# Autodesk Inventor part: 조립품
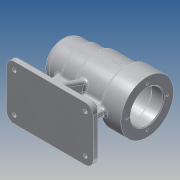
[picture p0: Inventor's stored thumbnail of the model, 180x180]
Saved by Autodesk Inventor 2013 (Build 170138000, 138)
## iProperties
Created: 2016-06
Part Number: 조립품
Material: 알루미늄 6061
Document SubType Name: Modeling
Designer: Administrator
Density: 2.71 g/cm^3
Mass: 669.883 g
Surface Area: 649.572 cm^2
Volume: 247.189 cm^3
Author: Administrator
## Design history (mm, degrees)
sketch "스케치1"
  geometry: L1 (56, 34)-(56, 0); L2 (56, 0)-(-56, 0); L3 (-56, 0)-(-56, 25); L4 (56, 34)-(28, 34); L5 (28, 34)-(28, 30); L6 (28, 30)-(-11, 30); L7 (-11, 30)-(-11, 27); L8 (-11, 27)-(-31, 27); L9 (-31, 27)-(-31, 25); L10 (-31, 25)-(-56, 25); 2 further points
  constraints: 20 end point, 5 parallel, 3 perpendicular, 1 coincident, 1 midpoint
  dimensions: "d0" = 112 distance between parallel lines of L1 L3; "d2" = 68 diameter of L4 L2; "d3" = 60 diameter of L6 L2; "d4" = 54 diameter of L8 L2; "d5" = 50 diameter of L10 L2; "d6" = 25 distance between parallel lines of L3 L9; "d7" = 45 distance between parallel lines of L7 L3; "d8" = 84 distance between parallel lines of L3 L5
sketch "스케치2"
  geometry: 1 further point
sketch "스케치3"
  geometry: 1 further point
revolve "회전1" stored, may be unused: angle "d9" = 90 deg
sketch "스케치4"
  geometry: L1 (-31, -25)-(-56, -25) reference; L2 (-56, -25)-(-56, 25) reference; L3 (-56, 25)-(-31, 25) reference; L4 (-31, 25)-(-31, 27) reference; L5 (-31, 27)-(-11, 27) reference; L6 (-11, 27)-(-11, 30) reference; L7 (-11, 30)-(28, 30) reference; L8 (28, 30)-(28, 34) reference; L9 (28, 34)-(56, 34) reference; L10 (56, 34)-(56, -34) reference; L11 (56, -34)-(28, -34) reference; L12 (28, -34)-(28, -30) reference; L13 (28, -30)-(-11, -30) reference; L14 (-11, -30)-(-11, -27) reference; L15 (-11, -27)-(-31, -27) reference; L16 (-31, -27)-(-31, -25) reference; L17 (-36, 0)-(-36, -60); L18 (-36, 0)-(36, 0); L19 (28, -34)-(28, 34) reference; L20 (36, 0)-(36, -60); L21 (-56, -60)-(56, -60); L22 (56, -60)-(56, -70); L23 (56, -70)-(-56, -70); L24 (-56, -70)-(-56, -60); 2 further points
  constraints: 14 end point, 4 parallel, 2 perpendicular, 2 point on line, 1 coincident, 1 horizontal, 1 midpoint, 1 vertical alignment
  dimensions: "d10" = 70 distance from line of point (0, 0) L23; "d11" = 10 distance between parallel lines of L23 L21; "d12" = 112 distance between parallel lines of L22 L24; "d13" = 20 distance of L17.end L21.start; "d14" = 20 distance of L21.end L20.end (derived)
  node "절단 모서리 투영1"
extrude "돌출1" join sketch "스케치4" stored distance "d15" = 8; taper "d16" = 0 deg
extrude "돌출2" join sketch "스케치4" stored distance "d17" = 70; taper "d18" = 0 deg
sketch "스케치5"
  geometry: L1 (-60, -4)-(-60, -35) reference; L2 (-60, -35)-(-70, -35) reference; L3 (-70, -35)-(-70, 35) reference; L4 (-70, 35)-(-60, 35) reference; L5 (-60, 35)-(-60, 4) reference; L6 (-60, 4)-(-29.732, 4) reference; L7 (-29.732, -4)-(-60, -4) reference; L8 (0, 6.162)-(-60, 28); L9 (-60, -35)-(-60, 35) reference; L10 (0, -6.162)-(-60, -28); L11 (0, 6.162)-(0, -6.162); A1 r 30 centre (0, 0) between (-29.732, -4) and (-29.732, 4) reference; 2 further points
  constraints: 6 end point, 2 point on line, 1 coincident, 1 midpoint, 1 parallel
  dimensions: "d19" = 110 deg angle of L8 L5; "d20" = 110 deg angle of L10 L1; "d21" = 7 distance of L8.end L4.end; "d22" = 7 distance of L1.end L10.end (derived)
extrude "돌출3" join sketch "스케치5" stored distance "d23" = 8; taper "d24" = 0 deg
sketch "스케치6"
  geometry: L1 (-56, 25)-(-31, 25) reference; L2 (-31, 25)-(-31, 27) reference; L3 (-31, 27)-(-11, 27) reference; L4 (-11, 27)-(-11, 30) reference; L5 (-11, 30)-(28, 30) reference; L6 (28, 30)-(28, 34) reference; L7 (28, 34)-(56, 34) reference; L8 (56, 34)-(56, -34) reference; L9 (56, -34)-(36, -34) reference; L10 (36, -34)-(36, -60) reference; L11 (36, -60)-(56, -60) reference; L12 (56, -60)-(56, -70) reference; L13 (56, -70)-(-56, -70) reference; L14 (-56, -70)-(-56, -60) reference; L15 (-56, -60)-(-36, -60) reference; L16 (-36, -60)-(-36, -25) reference; L17 (-36, -25)-(-56, -25) reference; L18 (-56, -25)-(-56, 25) reference; L19 (56, -34)-(56, 34) reference; L20 (-50, 0)-(-50, 10.5); L21 (-50, 10.5)-(-47, 10.5); L22 (-47, 10.5)-(-47, 16); L23 (-47, 16)-(-43, 16); L24 (-43, 16)-(-43, 17.5); L25 (-43, 17.5)-(-25, 17.5); L26 (-25, 17.5)-(-25, 21); L27 (-25, 21)-(-13, 21); L28 (-13, 21)-(-13, 24); L29 (-13, 24)-(41, 24); L30 (41, 24)-(41, 21); L31 (41, 21)-(56, 21); L32 (-50, 0)-(56, 0); L33 (56, 21)-(56, 0); 2 further points
  constraints: 28 end point, 8 parallel, 5 perpendicular, 2 midpoint, 1 collinear, 1 horizontal alignment, 1 point on line
  dimensions: "d30" = 3 distance between parallel lines of L22 L20; "d32" = 4 distance between parallel lines of L24 L22; "d33" = 18 distance between parallel lines of L26 L24; "d34" = 12 distance between parallel lines of L28 L26; "d35" = 54 distance between parallel lines of L30 L28; "d36" = 15 distance between parallel lines of L8 L30; "d37" = 21 diameter of L21 L32; "d38" = 32 diameter of L23 L32; "d39" = 35 diameter of L25 L32; "d40" = 42 diameter of L27 L32; "d41" = 48 diameter of L29 L32; "d42" = 42 diameter of L31 L32
revolve "회전2" sketch "스케치6" stored, may be unused: angle "d43" = 90 deg
fillet "모깎기1" dims "d44" = 10
chamfer "모따기1" distance "d45" = 4; stored, may be unused: second distance "d46" = 2, angle "d47" = 45 deg
chamfer "모따기2" distance "d48" = 1; stored, may be unused: second distance "d49" = 2, angle "d50" = 45 deg
fillet "모깎기2" dims "d51" = 3
fillet "모깎기3" dims "d52" = 0.3
fillet "모깎기4" dims "d53" = 3
sketch "스케치7"
  geometry: A1 r 6 centre (92, 6) between (92, 0) and (98, 6) reference; A2 r 6 centre (92, 56) between (98, 56) and (92, 62) reference; A3 r 6 centre (0, 56) between (0, 62) and (-6, 56) reference; A4 r 6 centre (0, 6) between (-6, 6) and (0, 0) reference; 5 further points
  constraints: 4 coincident
  dimensions: "d54" = 92 distance of point (92, 6) point (0, 6) (derived); "d55" = 50 distance of point (92, 56) A1.centre (derived)
hole "구멍1" sketch "스케치7" at (92, 6), (92, 56), (0, 6), (0, 56) diameter "d56" = 5; stored, may be unused: countersink angle "d60" = 90 deg, drill point angle "d62" = 118 deg; dims "d57" = 6, "d58" = 9, "d59" = 4, "d61" = 11.5
fillet "모깎기5" dims "d63" = 3
fillet "모깎기8" dims "d66" = 3
fillet "모깎기9" dims "d67" = 10
fillet "모깎기10" dims "d68" = 3
fillet "모깎기11" dims "d69" = 3
sketch "스케치8"
  geometry: C1 r 34 at (0, 0) reference; 1 further point
  constraints: 1 vertical alignment
  dimensions: "d70" = 26 distance of point (0, 26) C1.centre
hole "구멍2" sketch "스케치8" at (0, 26) diameter "d71" = 3.242; stored, may be unused: countersink angle "d75" = 90 deg, drill point angle "d77" = 118 deg; dims "d72" = 8, "d73" = 9, "d74" = 4, "d76" = 11
node "작업 평면1"
sketch "스케치9"
  geometry: L1 (56, -34)-(56, 34) reference; 2 further points
  constraints: 1 horizontal alignment, 1 other
  dimensions: "d82" = 48 distance from line of L1 point (8, 0)
feature "엠보싱1" sketch "스케치9" dims "d0" = 112, "d2" = 68, "d3" = 60, "d4" = 54, "d5" = 50, "d6" = 25, "d7" = 45, "d8" = 84, "d83" = 0.5, "d84" = 0
node "솔리드1"
pattern_circular "원형 패턴1" dims angle "d79" = 360 deg
node "절단 모서리 투영2"
node "절단 모서리 투영3"
